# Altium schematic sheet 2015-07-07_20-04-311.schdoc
size 308 x 170 mm; SheetNumber: 1; SheetTotal: 1
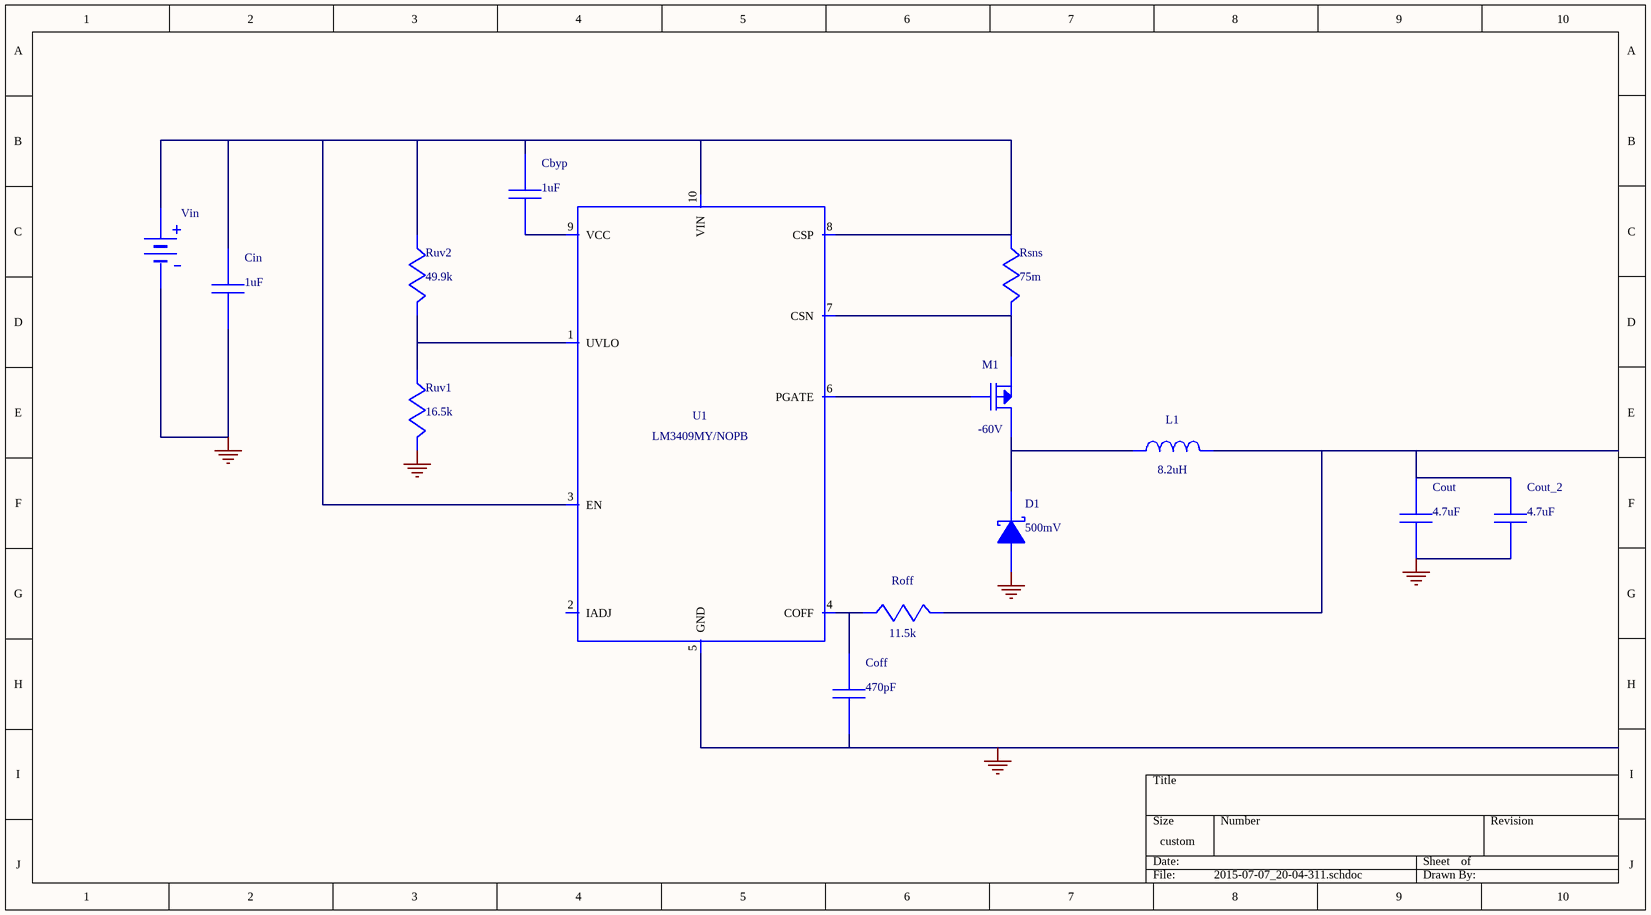
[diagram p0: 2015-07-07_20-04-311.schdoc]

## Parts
Cbyp  value 1uF  (hidden comment: C0603C105K8PACTU)
Cin  value 1uF  (hidden comment: C3216X5R1H105K)
Coff  value 470pF  (hidden comment: GRM033R71C471KA01D)
Cout  value 4.7uF  (hidden comment: GRM31CR71H475KA12L)
Cout_2  value 4.7uF  (hidden comment: GRM31CR71H475KA12L)
D1  value 500mV  (hidden comment: B340A-13-F)
L1  value 8.2uH  (hidden comment: SRP6540-8R2M)
M1  value -60V  (hidden comment: FDD5614P)
Roff  value 11.5k  (hidden comment: CRCW040211K5FKED)
Rsns  value 75m  (hidden comment: CSRN2010FK75L0)
Ruv1  value 16.5k  (hidden comment: CRCW040216K5FKED)
Ruv2  value 49.9k  (hidden comment: CRCW040249K9FKED)
U1  LM3409MY/NOPB
Vin  WB_BATTERY  (value not drawn)

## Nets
0: Cin.2 Coff.2 Cout.2 Cout_2.2 D1.2(A) Ruv1.1 U1.5(GND) U1.11(DAP) Vin.2(-)
NetCbyp_1: Cbyp.1 Cin.1 Rsns.2 Ruv2.2 U1.3(EN) U1.8(CSP) U1.10(VIN) Vin.1(+)
NetCbyp_2: Cbyp.2 U1.9(VCC)
NetCoff_1: Coff.1 Roff.2 U1.4(COFF)
NetCout_1: Cout.1 Cout_2.1 L1.2 Roff.1
NetD1_1: D1.1(K) L1.1 M1.2(Drain)
NetM1_1: M1.1(Gate) U1.6(PGATE)
NetM1_3: M1.3(Source) Rsns.1 U1.7(CSN)
NetRuv1_2: Ruv1.2 Ruv2.1 U1.1(UVLO)

Not connected (* = marked no-connect by the designer): U1 2(IADJ)

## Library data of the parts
Cbyp = C0603C105K8PACTU: Manufacturer Name: Kemet
Cin = C3216X5R1H105K: Manufacturer Name: TDK
Coff = GRM033R71C471KA01D: GRM033R71C471KA0; Manufacturer Name: MuRata
Cout Cout_2 = GRM31CR71H475KA12L: GRM31CR71H475KA1; Manufacturer Name: MuRata
D1 = B340A-13-F: Manufacturer Name: Diodes Inc.
L1 = SRP6540-8R2M: Unknown; Manufacturer Name: Bourns
M1 = FDD5614P: Manufacturer Name: Fairchild Semiconductor
Roff = CRCW040211K5FKED: Manufacturer Name: Vishay-Dale
Rsns = CSRN2010FK75L0: Manufacturer Name: Stackpole Electronics Inc
Ruv1 = CRCW040216K5FKED: Manufacturer Name: Vishay-Dale
Ruv2 = CRCW040249K9FKED: Manufacturer Name: Vishay-Dale
U1 = LM3409MY/NOPB: Manufacturer Name: Texas Instruments; Value: UNLISTED
Vin = WB_BATTERY: Value: UNLISTED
